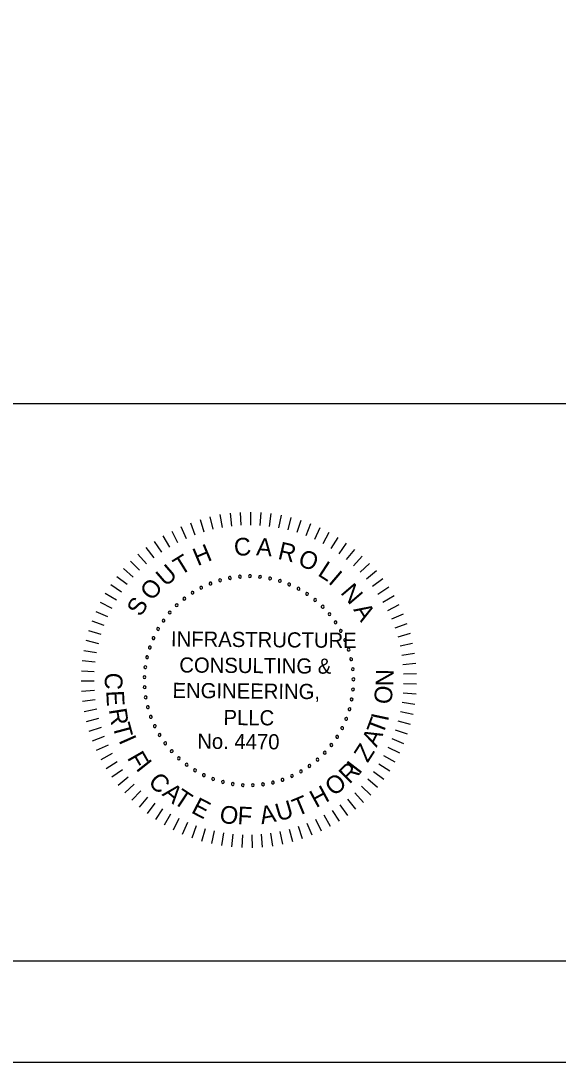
# Model space of a CAD drawing. Extents: x 96 to 240, y 601 to 689.
# Drawn here: x 196.67 to 207.27, y 601 to 621.55 of the extents above; entities that cross this region are included whole.
import ezdxf

# ---------------------------------------------------------------- set-up
doc = ezdxf.new("R2010")
doc.units = 0
for name, color, linetype in [('BR_BORDER LINES', 7, 'Continuous'), ('BR_TEXT', 7, 'Continuous'), ('Level 31', 7, 'Continuous')]:
    doc.layers.add(name, color=color, linetype=linetype)

msp = doc.modelspace()

# ---------------------------------------------------------------- linework, layer by layer
at = {"layer": 'BR_BORDER LINES'}
for p, q in [((186.375, 614.004), (207.836, 614.004)), ((103.173, 603.003), (237.837, 603.003))]:
    msp.add_line(p, q, dxfattribs=at)
at = {"layer": 'BR_TEXT'}
for p, q in [((200.401, 611.767), (200.46, 611.519)), ((200.599, 611.808), (200.643, 611.557)), ((200.798, 611.836), (200.827, 611.583)), ((201, 611.853), (201.013, 611.599)), ((201.202, 611.857), (201.199, 611.602)), ((201.403, 611.849), (201.386, 611.595)), ((201.604, 611.829), (201.571, 611.576)), ((201.804, 611.796), (201.755, 611.546)), ((202, 611.752), (201.937, 611.505)), ((199.828, 611.573), (199.931, 611.34)), ((200.015, 611.649), (200.104, 611.411)), ((200.206, 611.714), (200.28, 611.47)), ((202.194, 611.695), (202.116, 611.453)), ((202.384, 611.627), (202.291, 611.39)), ((202.57, 611.547), (202.463, 611.316)), ((199.469, 611.387), (199.6, 611.169)), ((199.646, 611.485), (199.763, 611.259)), ((202.75, 611.456), (202.629, 611.232)), ((202.925, 611.354), (202.79, 611.138)), ((199.136, 611.159), (199.293, 610.958)), ((199.299, 611.278), (199.443, 611.068)), ((203.093, 611.242), (202.945, 611.035)), ((203.253, 611.12), (203.093, 610.922)), ((198.981, 611.03), (199.149, 610.839)), ((203.406, 610.988), (203.235, 610.8)), ((198.695, 610.745), (198.885, 610.576)), ((198.833, 610.892), (199.013, 610.712)), ((203.551, 610.847), (203.368, 610.67)), ((198.565, 610.59), (198.766, 610.433)), ((203.687, 610.698), (203.493, 610.532)), ((203.813, 610.54), (203.61, 610.387)), ((198.446, 610.428), (198.655, 610.283)), ((203.93, 610.376), (203.718, 610.235)), ((198.336, 610.258), (198.554, 610.127)), ((204.036, 610.204), (203.816, 610.076)), ((198.149, 609.9), (198.381, 609.796)), ((198.237, 610.082), (198.463, 609.964)), ((204.132, 610.026), (203.904, 609.912)), ((198.072, 609.714), (198.31, 609.624)), ((204.217, 609.843), (203.982, 609.743)), ((198.007, 609.522), (198.25, 609.448)), ((204.29, 609.655), (204.05, 609.569)), ((197.953, 609.328), (198.2, 609.268)), ((204.352, 609.462), (204.107, 609.392)), ((197.911, 609.13), (198.162, 609.086)), ((204.402, 609.267), (204.153, 609.211)), ((204.44, 609.068), (204.188, 609.028)), ((197.882, 608.93), (198.135, 608.901)), ((204.465, 608.868), (204.212, 608.843)), ((197.864, 608.729), (198.119, 608.716)), ((204.479, 608.667), (204.224, 608.657)), ((197.859, 608.527), (198.114, 608.529)), ((204.48, 608.465), (204.225, 608.471)), ((197.867, 608.326), (198.121, 608.343)), ((204.469, 608.263), (204.215, 608.284)), ((197.886, 608.125), (198.139, 608.157)), ((204.445, 608.062), (204.193, 608.099)), ((197.918, 607.925), (198.168, 607.973)), ((204.41, 607.864), (204.161, 607.916)), ((197.962, 607.728), (198.209, 607.791)), ((204.362, 607.667), (204.117, 607.735)), ((198.018, 607.534), (198.26, 607.612)), ((198.086, 607.344), (198.323, 607.437)), ((204.303, 607.474), (204.062, 607.557)), ((198.165, 607.158), (198.396, 607.265)), ((204.231, 607.285), (203.996, 607.382)), ((198.255, 606.977), (198.479, 607.098)), ((204.055, 606.922), (203.833, 607.047)), ((204.149, 607.101), (203.92, 607.212)), ((198.356, 606.802), (198.572, 606.937)), ((203.951, 606.749), (203.737, 606.887)), ((198.468, 606.634), (198.675, 606.782)), ((198.589, 606.473), (198.787, 606.633)), ((203.836, 606.583), (203.631, 606.734)), ((198.72, 606.319), (198.909, 606.491)), ((203.577, 606.273), (203.392, 606.448)), ((203.712, 606.424), (203.516, 606.587)), ((198.861, 606.174), (199.038, 606.357)), ((199.01, 606.038), (199.176, 606.231)), ((203.283, 605.997), (203.12, 606.193)), ((203.434, 606.131), (203.26, 606.316)), ((199.167, 605.911), (199.32, 606.114)), ((199.331, 605.794), (199.472, 606.005)), ((203.124, 605.873), (202.973, 606.079)), ((199.502, 605.687), (199.63, 605.907)), ((199.68, 605.59), (199.794, 605.818)), ((202.604, 605.562), (202.494, 605.792)), ((202.784, 605.655), (202.659, 605.878)), ((202.957, 605.759), (202.819, 605.973)), ((199.863, 605.505), (199.963, 605.739)), ((200.051, 605.431), (200.136, 605.671)), ((200.243, 605.368), (200.314, 605.613)), ((202.037, 605.351), (201.97, 605.597)), ((202.231, 605.41), (202.149, 605.651)), ((202.42, 605.481), (202.323, 605.716)), ((200.438, 605.318), (200.494, 605.566)), ((200.636, 605.279), (200.677, 605.53)), ((200.836, 605.253), (200.862, 605.506)), ((201.038, 605.238), (201.048, 605.493)), ((201.24, 605.236), (201.234, 605.491)), ((201.441, 605.247), (201.42, 605.501)), ((201.642, 605.269), (201.606, 605.522)), ((201.841, 605.304), (201.789, 605.554))]:
    msp.add_line(p, q, dxfattribs=at)
for centre, start, end in [((200.601, 610.512), 16.1422, 196.1422), ((200.601, 610.512), 196.1422, 16.1422), ((200.795, 610.558), 10.6038, 190.6038), ((200.795, 610.558), 190.6038, 10.6038), ((200.993, 610.585), 5.0653, 185.0653), ((200.993, 610.585), 185.0653, 5.0653), ((201.192, 610.593), 359.5268, 179.5268), ((201.192, 610.593), 179.5268, 359.5268), ((201.391, 610.581), 353.9884, 173.9884), ((201.391, 610.581), 173.9884, 353.9884), ((201.588, 610.55), 348.4499, 168.4499), ((201.588, 610.55), 168.4499, 348.4499), ((201.781, 610.5), 162.9114, 342.9114), ((201.781, 610.5), 342.9114, 162.9114), ((200.231, 610.366), 27.2191, 207.2191), ((200.231, 610.366), 207.2191, 27.2191), ((200.412, 610.448), 21.6807, 201.6807), ((200.412, 610.448), 201.6807, 21.6807), ((201.968, 610.432), 157.373, 337.373), ((201.968, 610.432), 337.373, 157.373), ((202.148, 610.346), 151.8345, 331.8345), ((202.148, 610.346), 331.8345, 151.8345), ((199.896, 610.151), 38.2961, 218.2961), ((199.896, 610.151), 218.2961, 38.2961), ((200.058, 610.267), 32.7576, 212.7576), ((200.058, 610.267), 212.7576, 32.7576), ((202.319, 610.244), 146.2961, 326.2961), ((202.319, 610.244), 326.2961, 146.2961), ((202.479, 610.125), 140.7576, 320.7576), ((202.479, 610.125), 320.7576, 140.7576), ((199.608, 609.876), 49.373, 229.373), ((199.608, 609.876), 229.373, 49.373), ((199.745, 610.021), 43.8345, 223.8345), ((199.745, 610.021), 223.8345, 43.8345), ((202.627, 609.991), 135.2191, 315.2191), ((202.627, 609.991), 315.2191, 135.2191), ((199.485, 609.719), 54.9114, 234.9114), ((199.485, 609.719), 234.9114, 54.9114), ((202.761, 609.844), 129.6807, 309.6807), ((202.761, 609.844), 309.6807, 129.6807), ((202.88, 609.684), 124.1422, 304.1422), ((202.88, 609.684), 304.1422, 124.1422), ((199.378, 609.551), 60.4499, 240.4499), ((199.378, 609.551), 240.4499, 60.4499), ((202.984, 609.514), 118.6038, 298.6038), ((202.984, 609.514), 298.6038, 118.6038), ((199.288, 609.373), 65.9884, 245.9884), ((199.288, 609.373), 245.9884, 65.9884), ((203.07, 609.334), 113.0653, 293.0653), ((203.07, 609.334), 293.0653, 113.0653), ((199.216, 609.187), 71.5268, 251.5268), ((199.216, 609.187), 251.5268, 71.5268), ((203.139, 609.147), 107.5268, 287.5268), ((203.139, 609.147), 287.5268, 107.5268), ((199.161, 608.996), 77.0653, 257.0653), ((199.161, 608.996), 257.0653, 77.0653), ((203.189, 608.954), 101.9884, 281.9884), ((203.189, 608.954), 281.9884, 101.9884), ((199.126, 608.799), 82.6038, 262.6038), ((199.126, 608.799), 262.6038, 82.6038), ((203.221, 608.758), 96.4499, 276.4499), ((203.221, 608.758), 276.4499, 96.4499), ((199.109, 608.601), 88.1422, 268.1422), ((199.109, 608.601), 268.1422, 88.1422), ((203.233, 608.559), 90.9114, 270.9114), ((203.233, 608.559), 270.9114, 90.9114), ((199.112, 608.402), 93.6807, 273.6807), ((199.112, 608.402), 273.6807, 93.6807), ((203.226, 608.359), 85.373, 265.373), ((203.226, 608.359), 265.373, 85.373), ((199.134, 608.203), 99.2191, 279.2191), ((199.134, 608.203), 279.2191, 99.2191), ((199.175, 608.008), 284.7576, 104.7576), ((203.2, 608.162), 79.8345, 259.8345), ((203.2, 608.162), 259.8345, 79.8345), ((199.175, 608.008), 104.7576, 284.7576), ((199.235, 607.818), 110.2961, 290.2961), ((199.235, 607.818), 290.2961, 110.2961), ((203.155, 607.968), 74.2961, 254.2961), ((203.155, 607.968), 254.2961, 74.2961), ((199.312, 607.635), 115.8345, 295.8345), ((199.312, 607.635), 295.8345, 115.8345), ((203.092, 607.779), 68.7576, 248.7576), ((203.092, 607.779), 248.7576, 68.7576), ((199.407, 607.459), 121.373, 301.373), ((199.407, 607.459), 301.373, 121.373), ((202.912, 607.424), 57.6807, 237.6807), ((202.912, 607.424), 237.6807, 57.6807), ((203.01, 607.597), 63.2191, 243.2191), ((203.01, 607.597), 243.2191, 63.2191), ((199.519, 607.294), 126.9114, 306.9114), ((199.519, 607.294), 306.9114, 126.9114), ((202.797, 607.261), 52.1422, 232.1422), ((202.797, 607.261), 232.1422, 52.1422), ((199.646, 607.141), 132.4499, 312.4499), ((199.646, 607.141), 312.4499, 132.4499), ((199.787, 607), 137.9884, 317.9884), ((199.787, 607), 317.9884, 137.9884), ((202.667, 607.11), 46.6038, 226.6038), ((202.667, 607.11), 226.6038, 46.6038), ((199.941, 606.874), 143.5268, 323.5268), ((199.941, 606.874), 323.5268, 143.5268), ((202.366, 606.849), 35.5268, 215.5268), ((202.366, 606.849), 215.5268, 35.5268), ((202.523, 606.972), 41.0653, 221.0653), ((202.523, 606.972), 221.0653, 41.0653), ((200.107, 606.763), 149.0653, 329.0653), ((200.107, 606.763), 329.0653, 149.0653), ((200.282, 606.668), 154.6038, 334.6038), ((200.282, 606.668), 334.6038, 154.6038), ((200.466, 606.591), 160.1422, 340.1422), ((200.466, 606.591), 340.1422, 160.1422), ((201.835, 606.577), 18.9114, 198.9114), ((202.021, 606.65), 24.4499, 204.4499), ((202.021, 606.65), 204.4499, 24.4499), ((202.198, 606.741), 29.9884, 209.9884), ((202.198, 606.741), 209.9884, 29.9884), ((200.657, 606.532), 345.6807, 165.6807), ((200.657, 606.532), 165.6807, 345.6807), ((200.852, 606.492), 351.2191, 171.2191), ((200.852, 606.492), 171.2191, 351.2191), ((201.05, 606.471), 356.7576, 176.7576), ((201.05, 606.471), 176.7576, 356.7576), ((201.249, 606.469), 2.2961, 182.2961), ((201.249, 606.469), 182.2961, 2.2961), ((201.448, 606.486), 7.8345, 187.8345), ((201.448, 606.486), 187.8345, 7.8345), ((201.644, 606.522), 13.373, 193.373), ((201.644, 606.522), 193.373, 13.373), ((201.835, 606.577), 198.9114, 18.9114)]:
    msp.add_arc(centre, 0.028, start, end, dxfattribs=at)
at = {"layer": 'Level 31'}
msp.add_lwpolyline([(95.84, 601.004), (239.84, 601.004), (239.84, 689.004), (95.84, 689.004)], close=True, dxfattribs=at)

# ---------------------------------------------------------------- texts
at = {"layer": 'BR_TEXT'}
for s, height, rotation, p in [('C', 0.349, 4.7281, (200.89, 610.987)), ('A', 0.349, 355.6981, (201.308, 611.007)), ('H', 0.349, 22.7882, (200.158, 610.789)), ('R', 0.349, 346.6681, (201.725, 610.939)), ('T', 0.349, 31.8182, (199.819, 610.599)), ('O', 0.349, 337.638, (202.116, 610.819)), ('U', 0.349, 40.8482, (199.526, 610.374)), ('L', 0.349, 327.108, (202.511, 610.618)), ('O', 0.349, 49.8782, (199.258, 610.09)), ('I', 0.349, 319.578, (202.721, 610.466)), ('N', 0.349, 310.548, (202.965, 610.263)), ('S', 0.349, 58.9083, (199.036, 609.777)), ('A', 0.349, 301.5179, (203.225, 609.934)), ('INFRASTRUCTURE', 0.29909, 359.5268, (199.631, 609.207)), ('CONSULTING &', 0.29909, 359.5268, (199.796, 608.693)), ('C', 0.349, 267.025, (198.336, 608.698)), ('N', 0.349, 89.2085, (204.022, 608.419)), ('ENGINEERING,', 0.29909, 359.5268, (199.662, 608.191)), ('E', 0.349, 273.025, (198.354, 608.331)), ('O', 0.349, 83.2085, (203.978, 608.053)), ('R', 0.349, 279.025, (198.405, 607.962)), ('PLLC', 0.2991, 359.5268, (200.668, 607.657)), ('I', 0.349, 77.9093, (203.916, 607.716)), ('T', 0.349, 285.025, (198.475, 607.647)), ('T', 0.349, 69.3954, (203.813, 607.446)), ('I', 0.349, 293.7713, (198.593, 607.355)), ('No. 4470', 0.2991, 359.5268, (200.15, 607.189)), ('A', 0.349, 63.3954, (203.69, 607.204)), ('Z', 0.349, 57.3954, (203.514, 606.899)), ('F', 0.349, 299.7713, (198.758, 607.01)), ('I', 0.349, 308.5268, (198.927, 606.795)), ('R', 0.349, 44.5268, (203.153, 606.479)), ('I', 0.349, 52.3339, (203.35, 606.668)), ('C', 0.349, 314.5268, (199.164, 606.515)), ('O', 0.349, 38.5268, (202.846, 606.239)), ('A', 0.349, 320.5268, (199.441, 606.28)), ('T', 0.349, 326.5268, (199.658, 606.126)), ('H', 0.349, 28.5268, (202.494, 606.015)), ('E', 0.349, 332.5268, (200.013, 605.935)), ('T', 0.349, 22.5268, (202.121, 605.848)), ('O', 0.349, 350.5268, (200.573, 605.74)), ('F', 0.349, 356.5268, (200.939, 605.703)), ('A', 0.349, 10.5268, (201.419, 605.697)), ('U', 0.349, 16.5268, (201.754, 605.751))]:
    msp.add_text(s, height=height, rotation=rotation, dxfattribs=at).set_placement(p)

doc.saveas('drawing.dxf')
